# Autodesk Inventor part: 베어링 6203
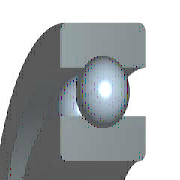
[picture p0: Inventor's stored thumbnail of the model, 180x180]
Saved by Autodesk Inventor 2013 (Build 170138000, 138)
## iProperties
IsCustomPart: 0
Company: 한국ATC센터
Created: 2015-11
Part Number: 베어링 6203
Material: 강철, 연강
Description: 깊은 그루브 볼 베어링
Document SubType Name: Modeling
Standard: KS B 2023
Designer: mdu
Standards Organization: KS
Language: ko-KR
Size Designation: 6203 - 17 x 40 x 12
Categories: <MemberInstance><Categories><Category DisplayName="샤프트 부품" InternalName="7f7aeb1f-a693-4053-b835-cee3144e0d98" Mnemonic="SHFT"><Category DisplayName="베어링" Inter
Density: 7.86 g/cm^3
Mass: 64.9809 g
Surface Area: 64.3582 cm^2
Volume: 8.26729 cm^3
Author: mdu
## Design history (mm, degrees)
sketch "스케치" dims "d0" = 5.98 (= -0.26 x WD + 0.26 x BD)
  geometry: L1 (3.01, 14.25)-(8.99, 14.25); L2 (6, 14.25)-(6, 11.26); L3 (6, 14.25)-(6, 17.24); L4 (3.778, 12.249)-(0, 12.249); L5 (0, 8.5)-(12, 8.5); L6 (3.778, 16.251)-(0, 16.251); L7 (0, 20)-(12, 20); L8 (12, 8.5)-(12, 12.249); L9 (8.222, 12.249)-(12, 12.249); L10 (8.222, 16.251)-(12, 16.251); L11 (12, 20)-(12, 16.251); L12 (-1.4, 0)-(8.4, 0) reference; L13 (0, -0.3)-(0, 5.3) reference
  constraints: 22 end point, 4 point on line, 2 collinear, 2 perpendicular, 2 symmetric about line, 1 midpoint, 1 parallel, 14 other
  dimensions: "d9" = 17 diameter of L5 L12 (= WD); "d11" = 40 diameter of L7 L12 (= BD); "d12" = 12 distance between parallel lines of L8 L13 (= KB); "d13" = 24.498 diameter of L9 L12 (= 0.326 x BD + 0.674 x WD)
revolve "본체" stored, may be unused: angle "d6" = 90 deg
revolve "볼" stored, may be unused: angle "d7" = 90 deg
pattern_circular "IDS_ARRAYBALL[SIMPL:T]" dims angle "d3" = 360 deg
body "Solid1"
fillet "모깎기1" dims "d1" = 0.6 (= KRS)
other parameters: "WD" = 17 [user parameter; used in 5 equation terms], "BD" = 40 [user parameter; used in 5 equation terms], "KB" = 12 [user parameter; used in 1 equation term], "KRS" = 0.6 [user parameter; used in 1 equation term], "d4" = 0, "d5" = 0, "d8" = 0, "d14" = 0, "d15" = 0, "BBA" = 0 [user parameter], "BC0" = 4750000 [user parameter], "BC" = 9560000 [user parameter], "WR" = 8.5 (= 0.5 x WD) [user parameter]
